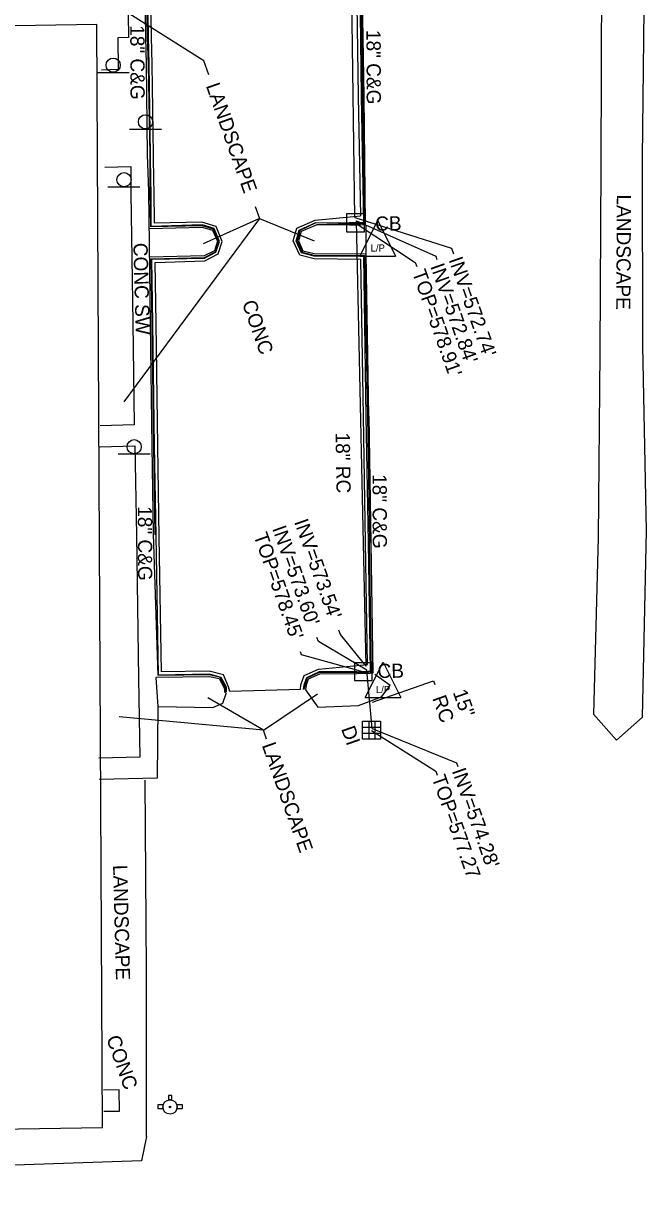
# Model space of a CAD drawing. Extents: x 2004847 to 2009016, y 1134161 to 1140101.
# Drawn here: x 2007247.9 to 2007423, y 1137397.3 to 1137729.8 of the extents above; entities that cross this region are included whole.
import ezdxf

# ---------------------------------------------------------------- set-up
doc = ezdxf.new("R2010")
doc.units = 0
for name, color, linetype in [('RD_EX_Bldg', 7, 'Continuous'), ('RD_EX_BldgApp', 7, 'Continuous'), ('RD_EX_Conc', 7, 'Continuous'), ('RD_EX_Curb', 7, 'Continuous'), ('RD_EX_DR_Inlet', 7, 'Continuous'), ('RD_EX_DR_Inlet_txCode', 7, 'Continuous'), ('RD_EX_DR_Pipe', 7, 'Continuous'), ('RD_EX_DR_Pipe_txCode', 7, 'Continuous'), ('RD_EX_Road', 7, 'Continuous'), ('RD_EX_UT', 7, 'Continuous'), ('RD_EX_VEG', 7, 'Continuous'), ('RD_Sketch3', 7, 'Continuous')]:
    doc.layers.add(name, color=color, linetype=linetype)

msp = doc.modelspace()

# ---------------------------------------------------------------- linework, layer by layer
at = {"layer": 'RD_EX_Bldg'}
msp.add_lwpolyline([(2006371.89, 1137715.52), (2006377.36, 1137405.37), (2007270.04, 1137419.53), (2007268.52, 1137729.51), (2007210.95, 1137728.61)], dxfattribs=at)
at = {"layer": 'RD_EX_BldgApp'}
for p, q in [((2007268.55, 1137716.07), (2007277.55, 1137716.07)), ((2007277.67, 1137700.14), (2007286.67, 1137700.14)), ((2007271.62, 1137683.88), (2007280.62, 1137683.88)), ((2007274.48, 1137608.82), (2007283.48, 1137608.82))]:
    msp.add_line(p, q, dxfattribs=at)
for centre in [(2007273.07, 1137718.1), (2007282.19, 1137702.17), (2007276.14, 1137685.9), (2007279, 1137610.84)]:
    msp.add_circle(centre, 2, dxfattribs=at)
at = {"layer": 'RD_EX_Conc'}
for points in [[(2007283.56, 1137645.52), (2007283.09, 1137682.57), (2007282.98, 1137685.29), (2007282.76, 1137692.86), (2007282.42, 1137718.35), (2007282.25, 1137726.01), (2007281.67, 1137766.99), (2007281.27, 1137788.33), (2007281.22, 1137805.08), (2007290.02, 1137805.25), (2007289.81, 1137817.8), (2007299.86, 1137813.61)], [(2007234.96, 1137809.42), (2007235.17, 1137804.52), (2007262.54, 1137804.84), (2007262.73, 1137799.9), (2007268.13, 1137799.95), (2007268.4, 1137797.65), (2007268.22, 1137795.13), (2007276.22, 1137795.16), (2007276.46, 1137780.75), (2007270.56, 1137779.3), (2007264.43, 1137773.46), (2007262.67, 1137766.49), (2007264.7, 1137759.65), (2007269.92, 1137754.63), (2007277.01, 1137752.81), (2007277.35, 1137725.93), (2007274.42, 1137725.77), (2007274.49, 1137716.92), (2007269.82, 1137716.73)], [(2007270.7, 1137689.47), (2007278.01, 1137689.59), (2007278.05, 1137682.05), (2007278.65, 1137645.72), (2007279, 1137617), (2007269.44, 1137616.74)], [(2007269.33, 1137610.78), (2007279.21, 1137611.1), (2007279.6, 1137585.99), (2007280.23, 1137545.69), (2007280.55, 1137523.62), (2007269.07, 1137523.32)], [(2007269.15, 1137517.43), (2007285.59, 1137517.82), (2007285.71, 1137537.82), (2007285.18, 1137545.95), (2007285.25, 1137546.08)], [(2007270.42, 1137424.1), (2007274.88, 1137424.11), (2007274.79, 1137430.03), (2007270.39, 1137429.97)]]:
    msp.add_lwpolyline(points, dxfattribs=at)
at = {"layer": 'RD_EX_Curb'}
msp.add_line((2007344.97, 1137619.48), (2007344.27, 1137665.03), dxfattribs=at)
for points in [[(2007284.94, 1137586.04), (2007284.56, 1137610.99), (2007284.06, 1137645.53), (2007283.78, 1137663.64), (2007298.79, 1137664.07), (2007301.89, 1137665.65), (2007302.84, 1137668.54), (2007301.28, 1137672.03), (2007298.18, 1137672.96), (2007283.7, 1137672.62), (2007283.49, 1137682.62), (2007283.5, 1137685.33), (2007283.47, 1137692.88), (2007283.04, 1137718.33), (2007282.7, 1137726.02), (2007282.12, 1137767.02), (2007281.75, 1137789.85), (2007295.54, 1137789.91), (2007299.53, 1137791.46), (2007300.51, 1137794.91), (2007300.31, 1137813.49), (2007299.35, 1137819.39)], [(2007337.76, 1137790.44), (2007341.06, 1137790.57), (2007341.68, 1137790.5), (2007341.68, 1137788.65), (2007342.34, 1137748.03), (2007342.81, 1137709.36), (2007343.5, 1137673.89), (2007339.46, 1137673.81)], [(2007337.83, 1137790.67), (2007340.98, 1137790.79), (2007341.9, 1137790.69), (2007341.91, 1137788.71), (2007342.6, 1137748.02), (2007343.2, 1137709.38), (2007343.78, 1137673.58), (2007342.66, 1137673.55), (2007339.46, 1137673.54)], [(2007344.01, 1137673.29), (2007343.62, 1137709.26), (2007343.04, 1137747.87), (2007342.34, 1137791.07)], [(2007305, 1137541.96), (2007304.92, 1137543.22), (2007303.46, 1137546), (2007300.15, 1137546.9), (2007285.86, 1137546.66), (2007285.15, 1137585.9), (2007284.75, 1137611), (2007284.22, 1137645.59), (2007283.93, 1137663.56), (2007298.77, 1137663.88), (2007301.95, 1137665.51), (2007302.98, 1137668.59), (2007301.48, 1137672.19), (2007298.1, 1137673.22), (2007283.81, 1137672.8), (2007283.73, 1137682.7), (2007283.67, 1137685.35), (2007283.59, 1137692.94), (2007283.18, 1137718.35), (2007283.06, 1137726.04), (2007282.35, 1137767.01)], [(2007344.87, 1137583.95), (2007344.22, 1137619.45), (2007343.56, 1137664.33), (2007329.58, 1137664.43), (2007326.01, 1137665.37), (2007324.53, 1137668.67), (2007325.36, 1137671.73), (2007330.11, 1137673.85), (2007339.46, 1137673.81)], [(2007339.46, 1137673.54), (2007330.07, 1137673.78), (2007325.57, 1137671.65), (2007324.86, 1137668.72), (2007326.21, 1137665.55), (2007329.56, 1137664.72), (2007343.77, 1137664.58), (2007344.62, 1137619.54), (2007345.14, 1137583.96)], [(2007339.54, 1137673.24), (2007330.39, 1137673.22), (2007325.94, 1137671.39), (2007325.23, 1137668.73), (2007326.45, 1137665.88), (2007329.59, 1137665.19), (2007344.27, 1137665.03)], [(2007339.54, 1137673.24), (2007342.64, 1137673.24), (2007344.01, 1137673.29)], [(2007283.3, 1137672.2), (2007298.08, 1137672.54), (2007301.01, 1137671.73), (2007302.43, 1137668.63), (2007301.6, 1137665.92), (2007298.69, 1137664.48), (2007283.38, 1137664.15)], [(2007285.7, 1137546.51), (2007284.47, 1137586.38), (2007284.08, 1137611.05), (2007283.56, 1137645.52)], [(2007344.97, 1137619.48), (2007345.55, 1137583.85), (2007346.09, 1137547.18)], [(2007341.6, 1137547.6), (2007344.92, 1137547.76), (2007345.4, 1137547.78), (2007344.87, 1137583.95)], [(2007341.63, 1137547.43), (2007344.89, 1137547.51), (2007345.68, 1137547.54), (2007345.14, 1137583.96)], [(2007304.85, 1137541.91), (2007304.66, 1137543.11), (2007303.24, 1137545.96), (2007300.22, 1137546.69), (2007285.7, 1137546.51)], [(2007341.6, 1137547.6), (2007331.02, 1137547.61), (2007327.44, 1137545.91), (2007326.71, 1137543.82), (2007326.54, 1137542.58)], [(2007341.63, 1137547.43), (2007331.02, 1137547.36), (2007327.54, 1137545.76), (2007326.94, 1137543.87), (2007326.71, 1137542.61)], [(2007341.73, 1137547.05), (2007331.06, 1137546.95), (2007327.93, 1137545.51), (2007327.34, 1137543.81), (2007327.18, 1137542.65)], [(2007346.09, 1137547.18), (2007345.36, 1137547.13), (2007341.73, 1137547.05)], [(2007285.25, 1137546.08), (2007300.22, 1137546.24), (2007302.92, 1137545.71), (2007304.27, 1137543.11), (2007304.44, 1137541.7)]]:
    msp.add_lwpolyline(points, dxfattribs=at)
at = {"layer": 'RD_EX_DR_Inlet'}
for p, q in [((2007343.73, 1137671.29), (2007343.73, 1137676.29)), ((2007345.9, 1137545.1), (2007345.9, 1137550.1)), ((2007344.93, 1137533.69), (2007344.93, 1137528.69)), ((2007346.63, 1137533.69), (2007346.63, 1137528.69)), ((2007343.23, 1137531.99), (2007348.23, 1137531.99)), ((2007343.23, 1137530.29), (2007348.23, 1137530.29))]:
    msp.add_line(p, q, dxfattribs=at)
for points in [[(2007343.73, 1137671.29), (2007343.73, 1137676.29), (2007338.73, 1137676.29), (2007338.73, 1137671.29)], [(2007345.9, 1137545.1), (2007345.9, 1137550.1), (2007340.9, 1137550.1), (2007340.9, 1137545.1)], [(2007343.23, 1137528.69), (2007343.23, 1137533.69), (2007348.23, 1137533.69), (2007348.23, 1137528.69)]]:
    msp.add_lwpolyline(points, close=True, dxfattribs=at)
at = {"layer": 'RD_EX_DR_Inlet_txCode'}
for points in [[(2007341.04, 1137675.28), (2007368.19, 1137666.66), (2007368.74, 1137665.11)], [(2007341.14, 1137673.75), (2007358.01, 1137662.67), (2007358.43, 1137661.48)], [(2007341.51, 1137674.39), (2007363.81, 1137664.43), (2007364.14, 1137663.5)], [(2007344.42, 1137548.04), (2007330.79, 1137556.11), (2007330.4, 1137557.2)], [(2007344.25, 1137549.15), (2007337, 1137558.04), (2007336.55, 1137559.32)], [(2007343.31, 1137547.56), (2007326.06, 1137552.34), (2007325.75, 1137553.23)], [(2007345.76, 1137531.13), (2007363.8, 1137519.69), (2007364.21, 1137518.55)], [(2007345.95, 1137531.65), (2007369.63, 1137521.96), (2007369.99, 1137520.94)]]:
    msp.add_lwpolyline(points, dxfattribs=at)
at = {"layer": 'RD_EX_DR_Pipe'}
for p, q in [((2007341.04, 1137675.28), (2007339.53, 1137788.98)), ((2007344.25, 1137549.15), (2007341.51, 1137674.39)), ((2007345.95, 1137531.65), (2007344.42, 1137548.04))]:
    msp.add_line(p, q, dxfattribs=at)
at = {"layer": 'RD_EX_DR_Pipe_txCode'}
msp.add_lwpolyline([(2007346.01, 1137539.07), (2007363.14, 1137545.08), (2007363.5, 1137544.05)], dxfattribs=at)
at = {"layer": 'RD_EX_Road'}
for points in [[(2007340.89, 1137788.53), (2007341.41, 1137748.06), (2007341.98, 1137709.35), (2007342.62, 1137675.79)], [(2007325.76, 1137542.6), (2007305.85, 1137542.02), (2007305.56, 1137543.39), (2007304.15, 1137546.7), (2007300.1, 1137547.72), (2007286.69, 1137547.58), (2007286.03, 1137585.45), (2007285.61, 1137611.01), (2007285.13, 1137645.62), (2007284.89, 1137662.63), (2007298.84, 1137663.14), (2007302.57, 1137665.03), (2007303.78, 1137668.57), (2007302.01, 1137672.79), (2007298.05, 1137674.02), (2007284.71, 1137673.7), (2007284.57, 1137682.77), (2007284.52, 1137685.38), (2007284.43, 1137692.92), (2007284.03, 1137718.38), (2007283.84, 1137726.07), (2007283.18, 1137767.08)], [(2007344.02, 1137583.95), (2007343.46, 1137619.49), (2007342.71, 1137663.51), (2007329.56, 1137663.64), (2007325.57, 1137664.67), (2007323.74, 1137668.71), (2007324.73, 1137672.25), (2007329.87, 1137674.57), (2007342.62, 1137675.79)], [(2007325.76, 1137542.6), (2007325.9, 1137543.93), (2007326.76, 1137546.52), (2007330.78, 1137548.32), (2007344.62, 1137549.66), (2007344.02, 1137583.95)]]:
    msp.add_lwpolyline(points, dxfattribs=at)
at = {"layer": 'RD_EX_UT'}
for p, q in [((2007342.49, 1137664.44), (2007347.49, 1137674.44)), ((2007347.49, 1137674.44), (2007352.49, 1137664.44)), ((2007342.49, 1137664.44), (2007352.49, 1137664.44)), ((2007343.98, 1137540.32), (2007348.98, 1137550.32)), ((2007348.98, 1137550.32), (2007353.98, 1137540.32)), ((2007343.98, 1137540.32), (2007353.98, 1137540.32)), ((2007288.62, 1137428.47), (2007288.62, 1137427.2)), ((2007289.62, 1137428.47), (2007288.62, 1137428.47)), ((2007289.62, 1137427.17), (2007289.62, 1137428.47)), ((2007287.16, 1137425.82), (2007285.6, 1137425.82)), ((2007285.6, 1137425.82), (2007285.6, 1137424.82)), ((2007285.6, 1137424.82), (2007287.12, 1137424.82)), ((2007292.6, 1137425.82), (2007290.99, 1137425.82)), ((2007291.03, 1137424.82), (2007292.6, 1137424.82)), ((2007292.6, 1137424.82), (2007292.6, 1137425.82))]:
    msp.add_line(p, q, dxfattribs=at)
for radius in [2, 0.25]:
    msp.add_circle((2007289.07, 1137425.25), radius, dxfattribs=at)
for start, end in [(74.2455, 103.2128), (163.3387, 192.315), (347.685, 16.6613)]:
    msp.add_arc((2007289.07, 1137425.25), 2, start, end, dxfattribs=at)
at = {"layer": 'RD_EX_VEG'}
msp.add_line((2007344.23, 1137665.23), (2007344.19, 1137673.02), dxfattribs=at)
for points in [[(2007410.37, 1137743.47), (2007410.18, 1137690.03), (2007409.95, 1137637.46), (2007409.42, 1137585.36), (2007408.17, 1137535.72), (2007414.6, 1137528.33), (2007421.96, 1137534.86), (2007423.01, 1137587.19), (2007422.06, 1137639.22), (2007421.92, 1137692.08), (2007422.52, 1137742.25), (2007421, 1137790.99), (2007414.16, 1137799.73), (2007407.47, 1137793.25), (2007410.37, 1137743.47)], [(2007327.19, 1137542.47), (2007330.64, 1137537.62), (2007342.06, 1137538.15), (2007348.53, 1137540.51), (2007351.01, 1137543.78), (2007346.66, 1137546.79)], [(2007285.71, 1137537.82), (2007301.07, 1137537.58), (2007303.96, 1137538.79), (2007304.93, 1137541.75)], [(2007282.5, 1137416.98), (2007282.47, 1137463.59), (2007282.07, 1137517.11)], [(2007282.5, 1137416.98), (2007281.09, 1137410.1), (2007242.65, 1137408.85), (2007161.61, 1137408.11), (2007074.33, 1137407.29), (2006993.94, 1137406.09), (2006904.98, 1137405.1), (2006825.9, 1137403.95), (2006734.64, 1137402.12), (2006651.81, 1137401.28), (2006571.17, 1137400.1), (2006488.04, 1137397.36), (2006412.6, 1137397.32), (2006371.03, 1137398.69)]]:
    msp.add_lwpolyline(points, dxfattribs=at)
at = {"layer": 'RD_Sketch3'}
for p, q in [((2007314.24, 1137675.01), (2007276.11, 1137623.43)), ((2007314.24, 1137675.01), (2007298.43, 1137667.89)), ((2007315.33, 1137531.18), (2007299.72, 1137540.24)), ((2007315.33, 1137531.18), (2007274.81, 1137534.91))]:
    msp.add_line(p, q, dxfattribs=at)
for points in [[(2007299.97, 1137715.42), (2007298.59, 1137719.32), (2007272.43, 1137735.8)], [(2007313.05, 1137678.38), (2007314.24, 1137675.01), (2007329.64, 1137668.69)], [(2007316.23, 1137528.64), (2007315.33, 1137531.18), (2007330.56, 1137541.38)]]:
    msp.add_lwpolyline(points, dxfattribs=at)

# ---------------------------------------------------------------- texts
at = {"layer": 'RD_EX_DR_Inlet_txCode'}
for s, rotation, p in [('CB', 0.8247, (2007346.78, 1137671.56)), ("INV=572.74'", 289.4494, (2007367.38, 1137663.43)), ("TOP=578.91'", 289.4494, (2007357.08, 1137659.83)), ("INV=572.84'", 289.4494, (2007362.2, 1137661.57)), ("INV=573.54'", 289.4494, (2007323.93, 1137589.74)), ("TOP=578.45'", 289.4494, (2007312.51, 1137585.92)), ("INV=573.60'", 289.4494, (2007317.75, 1137587.88)), ('CB', 0.8247, (2007347.45, 1137545.82)), ('DI', 289.4494, (2007337.14, 1137531.56)), ("INV=574.28'", 289.4494, (2007368.29, 1137519.74)), ('TOP=577.27', 289.4494, (2007362.61, 1137517.81))]:
    msp.add_text(s, height=4, rotation=rotation, dxfattribs=at).set_placement(p)
at = {"layer": 'RD_EX_DR_Pipe_txCode'}
for s, rotation, p in [('18" RC', 270.9063, (2007335.62, 1137614.8)), ('RC', 289.4494, (2007362.77, 1137540.17)), ('15"', 289.4494, (2007368.55, 1137541.84))]:
    msp.add_text(s, height=4, rotation=rotation, dxfattribs=at).set_placement(p)
at = {"layer": 'RD_EX_UT'}
for p in [(2007345.48, 1137665.72), (2007346.97, 1137541.61)]:
    msp.add_text('L/P', height=2, dxfattribs=at).set_placement(p)
at = {"layer": 'RD_Sketch3'}
for s, rotation, p in [('18" C&G', 270.1683, (2007277.89, 1137729.33)), ('18" C&G', 270.1683, (2007344.31, 1137728)), ('LANDSCAPE', 289.4494, (2007299.11, 1137712.34)), ('LANDSCAPE', 269.6482, (2007414.72, 1137681.76)), ('CONC SW', 271.5449, (2007278.75, 1137668.12)), ('CONC', 289.4494, (2007309.25, 1137651.25)), ('18" C&G', 270.1683, (2007346.01, 1137603.14)), ('18" C&G', 270.1683, (2007280.02, 1137594.12)), ('LANDSCAPE', 289.4494, (2007314.84, 1137526.94)), ('LANDSCAPE', 271.4688, (2007273.05, 1137493.27)), ('CONC', 289.4494, (2007271.09, 1137444.6))]:
    msp.add_text(s, height=4, rotation=rotation, dxfattribs=at).set_placement(p)

doc.saveas('drawing.dxf')
